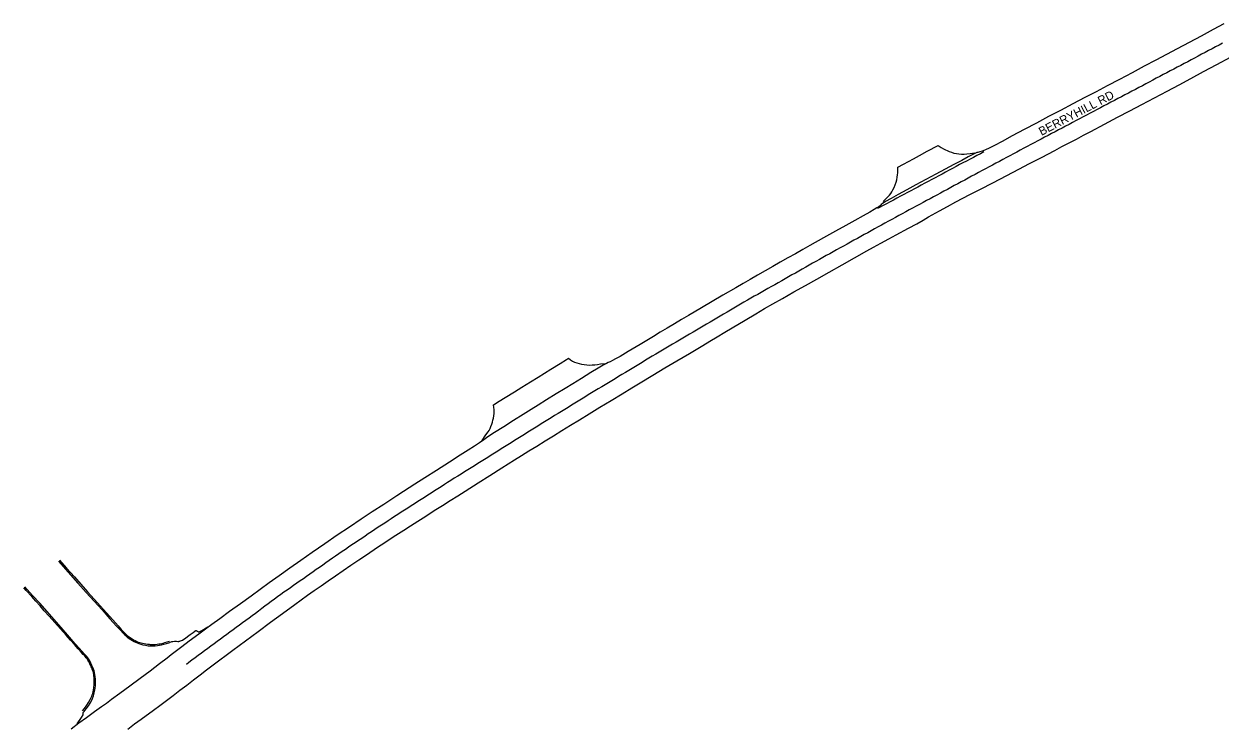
# Model space of a CAD drawing. Extents: x 1961683 to 1977751, y 798292 to 805767.
# Drawn here: x 1964029 to 1964786, y 800806 to 801250 of the extents above; entities that cross this region are included whole.
import ezdxf

# ---------------------------------------------------------------- set-up
doc = ezdxf.new("R2010")
doc.units = 0
for name, color, linetype in [('RD_EX_Road', 7, 'Continuous'), ('RD_EX_Road_Paint', 7, 'Continuous'), ('RD_TX_RoadID', 7, 'Continuous')]:
    doc.layers.add(name, color=color, linetype=linetype)

msp = doc.modelspace()

# ---------------------------------------------------------------- linework, layer by layer
at = {"layer": 'RD_EX_Road'}
for points in [[(1964788.54, 801250.42), (1964781.89, 801246.79), (1964774.38, 801242.74), (1964766.61, 801238.62), (1964759.07, 801234.65), (1964752.26, 801231.05), (1964745.53, 801227.48), (1964738.24, 801223.57), (1964730.54, 801219.46), (1964722.57, 801215.24), (1964714.81, 801211.15), (1964707.73, 801207.41), (1964700.69, 801203.7), (1964693.06, 801199.71), (1964685.24, 801195.62), (1964677.66, 801191.63), (1964670.04, 801187.61), (1964662.09, 801183.39), (1964654.57, 801179.38), (1964648.22, 801175.97), (1964643.28, 801173.36), (1964639.97, 801171.7), (1964637.64, 801170.66), (1964635.66, 801169.85), (1964634.07, 801169.3), (1964632.91, 801169.02), (1964632.3, 801168.84), (1964630.14, 801167.85), (1964626.81, 801166.08), (1964622.62, 801163.89), (1964617.66, 801161.34), (1964612.14, 801158.43), (1964606.14, 801155.19), (1964599.93, 801151.85), (1964593.63, 801148.49), (1964587.76, 801145.27), (1964582.46, 801142.26), (1964577.98, 801139.77), (1964574.44, 801137.84), (1964572.24, 801136.45), (1964571.67, 801135.95), (1964570.88, 801135.16), (1964570.05, 801134.51), (1964568.89, 801133.78), (1964567.14, 801132.73), (1964564.36, 801131.11), (1964560.13, 801128.69), (1964554.93, 801125.76), (1964549.25, 801122.63), (1964542.75, 801119.04), (1964535.08, 801114.74), (1964526.5, 801109.92), (1964521.98, 801107.38), (1964517.29, 801104.76), (1964512.51, 801102.09), (1964507.73, 801099.39), (1964502.93, 801096.67), (1964498.13, 801093.92), (1964493.36, 801091.18), (1964488.68, 801088.49), (1964484.09, 801085.84), (1964479.59, 801083.24), (1964471.4, 801078.46), (1964464.65, 801074.47), (1964457.88, 801070.46), (1964449.61, 801065.62), (1964445.12, 801062.99), (1964440.63, 801060.34), (1964436.15, 801057.68), (1964431.69, 801055), (1964427.3, 801052.36), (1964418.95, 801047.33), (1964411.42, 801042.79), (1964406.25, 801039.72), (1964403.43, 801038.11), (1964401.42, 801037.01), (1964399.93, 801036.24), (1964398.71, 801035.72), (1964397.58, 801035.29), (1964395.57, 801034.2), (1964392.45, 801032.29), (1964387.78, 801029.42), (1964381.8, 801025.74), (1964376.29, 801022.36), (1964371.35, 801019.35), (1964365.78, 801015.93), (1964359.6, 801012.14), (1964354.34, 801008.87), (1964349.95, 801006.12), (1964344.77, 801002.87), (1964338.69, 800999.04), (1964332.56, 800995.15), (1964326.74, 800991.42), (1964322.53, 800988.64), (1964319.86, 800986.79), (1964317.14, 800984.91), (1964314.02, 800982.82), (1964310.05, 800980.25), (1964305.03, 800977.06), (1964298.22, 800972.73), (1964289.92, 800967.44), (1964282.59, 800962.77), (1964276.3, 800958.74), (1964268.98, 800954), (1964264.8, 800951.27), (1964256.57, 800945.88), (1964249.29, 800941.1), (1964242.29, 800936.48), (1964234.87, 800931.56), (1964227.13, 800926.37), (1964219.14, 800920.91), (1964211.29, 800915.49), (1964203.98, 800910.41), (1964197.03, 800905.53), (1964190.29, 800900.72), (1964183.98, 800896.17), (1964178.3, 800892.03), (1964172.48, 800887.77), (1964165.72, 800882.88), (1964158.87, 800877.91), (1964152.78, 800873.45), (1964147.65, 800869.67), (1964143.69, 800866.77), (1964140.35, 800864.33), (1964137.1, 800861.91), (1964133.39, 800859.13), (1964128.65, 800855.62), (1964124.35, 800852.42), (1964121.92, 800850.56), (1964119.34, 800848.54), (1964114.55, 800844.84), (1964108.51, 800840.24), (1964102.18, 800835.5), (1964095.76, 800830.73), (1964089.43, 800826.05), (1964084.15, 800822.17), (1964080.86, 800819.8), (1964077.85, 800817.64), (1964073.39, 800814.4), (1964068.3, 800810.7), (1964063.42, 800807.16), (1964058.54, 800803.54)], [(1964094.49, 800803.53), (1964098.77, 800806.72), (1964102.88, 800809.76), (1964110.77, 800815.54), (1964114.8, 800818.53), (1964118.94, 800821.63), (1964123.18, 800824.84), (1964127.46, 800828.11), (1964131.72, 800831.36), (1964135.96, 800834.6), (1964140.18, 800837.83), (1964144.38, 800841.03), (1964148.54, 800844.19), (1964152.68, 800847.31), (1964156.78, 800850.4), (1964160.86, 800853.45), (1964164.92, 800856.48), (1964168.96, 800859.48), (1964176.97, 800865.4), (1964184.77, 800871.15), (1964192.42, 800876.76), (1964200.24, 800882.44), (1964208.32, 800888.26), (1964212.54, 800891.25), (1964216.88, 800894.31), (1964221.36, 800897.43), (1964225.97, 800900.63), (1964230.74, 800903.91), (1964235.67, 800907.28), (1964240.75, 800910.73), (1964245.52, 800913.95), (1964252.67, 800918.78), (1964257.23, 800921.81), (1964262.58, 800925.26), (1964269.37, 800929.57), (1964273.49, 800932.21), (1964278.11, 800935.19), (1964283.24, 800938.51), (1964288.54, 800941.94), (1964293.68, 800945.24), (1964298.66, 800948.4), (1964303.47, 800951.42), (1964308.07, 800954.3), (1964316.4, 800959.57), (1964323.79, 800964.29), (1964331.32, 800969.07), (1964339.31, 800974.06), (1964343.72, 800976.81), (1964348.45, 800979.75), (1964353.51, 800982.88), (1964358.75, 800986.13), (1964364.05, 800989.4), (1964369.41, 800992.72), (1964374.83, 800996.06), (1964380.52, 800999.57), (1964386.72, 801003.36), (1964393.41, 801007.43), (1964400.6, 801011.8), (1964407.59, 801016.03), (1964413.68, 801019.72), (1964418.88, 801022.87), (1964427, 801027.8), (1964434.58, 801032.36), (1964442.13, 801036.85), (1964450.12, 801041.61), (1964458.66, 801046.69), (1964463.15, 801049.38), (1964467.81, 801052.15), (1964472.63, 801055.03), (1964477.32, 801057.83), (1964485.49, 801062.69), (1964492.13, 801066.62), (1964497.8, 801069.95), (1964502.88, 801072.91), (1964509.01, 801076.42), (1964516.28, 801080.55), (1964523.59, 801084.67), (1964530.85, 801088.74), (1964538.61, 801093.11), (1964546.84, 801097.77), (1964554.78, 801102.22), (1964562.51, 801106.5), (1964566.78, 801108.86), (1964571.4, 801111.39), (1964576.36, 801114.1), (1964581.18, 801116.73), (1964588.89, 801120.92), (1964594.2, 801123.81), (1964598.14, 801126.08), (1964601.58, 801128.16), (1964608.56, 801132.04), (1964613.63, 801134.78), (1964618.94, 801137.61), (1964627.74, 801142.2), (1964634.61, 801145.64), (1964642.37, 801149.63), (1964651.14, 801154.26), (1964658.9, 801158.34), (1964665.6, 801161.85), (1964673.09, 801165.79), (1964681.59, 801170.27), (1964686.04, 801172.62), (1964690.58, 801175.02), (1964695.22, 801177.47), (1964699.86, 801179.92), (1964704.39, 801182.32), (1964713.12, 801186.93), (1964721.35, 801191.29), (1964729.03, 801195.33), (1964736.66, 801199.35), (1964744.71, 801203.59), (1964752.73, 801207.83), (1964760.26, 801211.84), (1964767.79, 801215.87), (1964775.78, 801220.18), (1964784.19, 801224.71), (1964792.92, 801229.36)], [(1964572.94, 801137.8), (1964575.36, 801140.33), (1964576.79, 801141.93), (1964577.65, 801143.03), (1964578.34, 801144.09), (1964578.99, 801145.29), (1964579.73, 801146.82), (1964580.44, 801148.48), (1964581, 801150.11), (1964581.44, 801151.68), (1964581.81, 801153.19), (1964582.05, 801154.66), (1964582.15, 801156.09), (1964582.17, 801157.67), (1964582.19, 801159.6), (1964585.84, 801161.54), (1964588.93, 801163.25), (1964592.06, 801165), (1964595.81, 801167.06), (1964600.81, 801169.73), (1964607.68, 801173.3), (1964609.59, 801172.16), (1964611.05, 801171.31), (1964612.25, 801170.66), (1964613.39, 801170.11), (1964614.63, 801169.59), (1964616.11, 801169.06), (1964617.7, 801168.58), (1964619.24, 801168.25), (1964620.81, 801168.03), (1964622.5, 801167.9), (1964624.22, 801167.89), (1964625.88, 801167.99), (1964627.95, 801168.25), (1964630.89, 801168.74)], [(1964318.91, 800986.48), (1964320.79, 800989.45), (1964321.84, 800990.73), (1964322.63, 800991.79), (1964323.27, 800992.78), (1964323.85, 800993.89), (1964324.43, 800995.27), (1964324.95, 800996.71), (1964325.35, 800998), (1964325.67, 800999.26), (1964325.96, 801000.63), (1964326.21, 801002.05), (1964326.38, 801003.49), (1964326.45, 801004.85), (1964326.4, 801006.06), (1964326.27, 801007.38), (1964326.11, 801009.08), (1964329.69, 801011.28), (1964333.46, 801013.6), (1964339.4, 801017.31), (1964343.92, 801020.14), (1964349.49, 801023.63), (1964354.37, 801026.6), (1964362.42, 801031.52), (1964368.27, 801035.12), (1964372.27, 801037.64), (1964373.6, 801038.51), (1964374.84, 801037.58), (1964376.13, 801036.74), (1964377.45, 801036.04), (1964378.82, 801035.54), (1964380.26, 801035.17), (1964381.8, 801034.84), (1964383.43, 801034.56), (1964385.17, 801034.34), (1964386.93, 801034.22), (1964388.65, 801034.25), (1964390.3, 801034.38), (1964391.89, 801034.58), (1964393.74, 801034.93), (1964396.9, 801035.23)], [(1964050.52, 800909.9), (1964056.68, 800902.99), (1964062.83, 800896.07), (1964068.15, 800890.09), (1964073.19, 800884.47), (1964078.12, 800878.98), (1964083.15, 800873.42), (1964087.34, 800868.79), (1964089.78, 800866.1), (1964091.25, 800864.52), (1964092.55, 800863.23), (1964093.54, 800862.31), (1964094.06, 800861.84), (1964094.52, 800861.49), (1964095.34, 800860.91), (1964096.34, 800860.25), (1964097.35, 800859.62), (1964098.37, 800859.04), (1964099.39, 800858.51), (1964100.42, 800858.05), (1964101.47, 800857.65), (1964102.63, 800857.28), (1964104.01, 800856.94), (1964105.56, 800856.63), (1964107.26, 800856.35), (1964108.93, 800856.18), (1964110.39, 800856.15), (1964111.77, 800856.25), (1964113.19, 800856.43), (1964114.57, 800856.65), (1964115.81, 800856.88), (1964117.16, 800857.21), (1964118.87, 800857.71), (1964120.33, 800858.17), (1964120.95, 800858.35), (1964121.31, 800858.48), (1964121.95, 800858.77), (1964122.38, 800858.93), (1964122.87, 800859.04), (1964124.04, 800859.15), (1964125.19, 800859.14), (1964126.06, 800859.1), (1964126.69, 800859.08), (1964126.95, 800859.11), (1964127.37, 800859.22), (1964127.86, 800859.36), (1964128.45, 800859.54), (1964129.15, 800859.87), (1964129.98, 800860.38), (1964131.01, 800861.12), (1964132.29, 800862.1), (1964133.91, 800863.35), (1964135.74, 800864.75), (1964136.81, 800865.57), (1964137.08, 800865.77), (1964137.17, 800865.81), (1964137.26, 800865.85), (1964137.47, 800865.91), (1964137.57, 800865.93), (1964137.67, 800865.93), (1964137.76, 800865.93), (1964137.85, 800865.92), (1964137.94, 800865.89), (1964138.03, 800865.85), (1964138.21, 800865.73), (1964138.46, 800865.54), (1964138.77, 800865.29), (1964138.91, 800865.2), (1964139.03, 800865.14), (1964139.13, 800865.11), (1964139.23, 800865.1), (1964139.36, 800865.11), (1964139.7, 800865.19), (1964141.24, 800866.04), (1964145.08, 800868.39)], [(1964051.21, 800910.52), (1964055.68, 800905.53), (1964060.61, 800899.99), (1964064.77, 800895.3), (1964069, 800890.54), (1964073.16, 800885.88), (1964077.11, 800881.48), (1964081, 800877.14), (1964085, 800872.66), (1964088.35, 800868.9), (1964090.32, 800866.69), (1964091.53, 800865.36), (1964092.6, 800864.25), (1964093.46, 800863.41), (1964094.06, 800862.86), (1964094.62, 800862.41), (1964095.37, 800861.86), (1964096.23, 800861.27), (1964097.16, 800860.67), (1964098.14, 800860.09), (1964099.16, 800859.55), (1964100.16, 800859.07), (1964101.1, 800858.68), (1964102.01, 800858.36), (1964102.91, 800858.11), (1964103.84, 800857.9), (1964104.81, 800857.72), (1964105.83, 800857.55), (1964106.9, 800857.38), (1964107.89, 800857.25), (1964108.68, 800857.17), (1964109.5, 800857.13), (1964110.61, 800857.12), (1964111.82, 800857.16), (1964112.95, 800857.28), (1964114.01, 800857.45), (1964115, 800857.61), (1964115.92, 800857.8), (1964116.75, 800858.01), (1964117.92, 800858.36), (1964120.88, 800859.26)], [(1964065.67, 800815.04), (1964066.94, 800816.64), (1964068.42, 800818.61), (1964069.54, 800820.32), (1964070.61, 800822.23), (1964071.25, 800823.42), (1964071.64, 800824.26), (1964071.95, 800825.15), (1964072.22, 800826.08), (1964072.47, 800827.06), (1964072.7, 800828.26), (1964072.95, 800829.84), (1964073.13, 800831.5), (1964073.19, 800832.94), (1964073.17, 800834.18), (1964073.13, 800835.24), (1964073.07, 800836.21), (1964072.97, 800837.2), (1964072.82, 800838.17), (1964072.63, 800839.08), (1964072.4, 800839.93), (1964072.17, 800840.73), (1964071.92, 800841.49), (1964071.63, 800842.21), (1964071.29, 800842.98), (1964070.9, 800843.85), (1964070.46, 800844.78), (1964069.99, 800845.71), (1964069.54, 800846.54), (1964069.17, 800847.18), (1964068.83, 800847.71), (1964068.49, 800848.21), (1964068.12, 800848.69), (1964067.71, 800849.18), (1964067.12, 800849.82), (1964066.23, 800850.8), (1964064.9, 800852.28), (1964062.99, 800854.42), (1964060.69, 800857), (1964058.21, 800859.79), (1964055.32, 800863.02), (1964051.81, 800866.96), (1964048.12, 800871.12), (1964044.68, 800874.99), (1964041.56, 800878.51), (1964038.83, 800881.59), (1964036.24, 800884.51), (1964033.56, 800887.53), (1964030.1, 800891.4), (1964028.63, 800893.02)], [(1964062.32, 800806.88), (1964065.05, 800810.85), (1964066.08, 800812.53), (1964066.21, 800812.99), (1964066.23, 800813.16), (1964066.22, 800813.29), (1964066.19, 800813.5), (1964066.15, 800813.69), (1964066.14, 800813.78), (1964066.15, 800813.86), (1964066.18, 800813.94), (1964066.23, 800814.02), (1964066.73, 800814.65), (1964068.01, 800816.25), (1964069.49, 800818.22), (1964070.61, 800819.93), (1964071.45, 800821.47), (1964072.08, 800822.95), (1964072.61, 800824.53), (1964073.12, 800826.41), (1964073.55, 800828.24), (1964073.81, 800829.71), (1964073.94, 800830.96), (1964073.99, 800832.13), (1964074, 800833.2), (1964073.97, 800834.18), (1964073.91, 800835.27), (1964073.8, 800836.67), (1964073.64, 800838.12), (1964073.4, 800839.36), (1964073.11, 800840.43), (1964072.79, 800841.39), (1964072.36, 800842.46), (1964071.74, 800843.87), (1964071.03, 800845.35), (1964070.34, 800846.66), (1964069.51, 800847.96), (1964068.38, 800849.4), (1964067.02, 800850.99), (1964065.5, 800852.72), (1964063.62, 800854.85), (1964061.18, 800857.62), (1964056.31, 800863.21), (1964052.26, 800867.9), (1964047.87, 800872.86), (1964043.26, 800878.01), (1964038.62, 800883.2), (1964034.15, 800888.21), (1964030.76, 800892.01), (1964029.31, 800893.63)]]:
    msp.add_lwpolyline(points, dxfattribs=at)
at = {"layer": 'RD_EX_Road_Paint'}
for points in [[(1964787.8, 801238.23), (1964785.59, 801237.05), (1964783.39, 801235.87), (1964781.19, 801234.69), (1964778.98, 801233.51), (1964776.78, 801232.33), (1964774.57, 801231.15), (1964772.37, 801229.97), (1964770.16, 801228.8), (1964767.95, 801227.63), (1964765.75, 801226.46), (1964763.54, 801225.29), (1964761.33, 801224.12), (1964759.12, 801222.95), (1964756.91, 801221.78), (1964754.7, 801220.61), (1964752.5, 801219.44), (1964750.29, 801218.27), (1964748.08, 801217.1), (1964745.87, 801215.93), (1964743.66, 801214.76), (1964741.45, 801213.59), (1964739.25, 801212.42), (1964737.04, 801211.25), (1964734.83, 801210.09), (1964732.62, 801208.92), (1964730.41, 801207.75), (1964728.2, 801206.59), (1964725.99, 801205.42), (1964723.78, 801204.25), (1964721.57, 801203.09), (1964719.36, 801201.92), (1964717.15, 801200.75), (1964714.94, 801199.59), (1964712.73, 801198.42), (1964710.52, 801197.25), (1964708.31, 801196.09), (1964706.1, 801194.92), (1964703.89, 801193.76), (1964701.68, 801192.59), (1964699.47, 801191.43), (1964697.26, 801190.26), (1964695.05, 801189.1), (1964692.84, 801187.93), (1964690.63, 801186.77), (1964688.42, 801185.6), (1964686.21, 801184.44), (1964684, 801183.27), (1964681.79, 801182.11), (1964679.58, 801180.94), (1964677.37, 801179.78), (1964675.16, 801178.61), (1964672.95, 801177.45), (1964670.74, 801176.28), (1964668.53, 801175.11), (1964666.33, 801173.93), (1964664.13, 801172.75), (1964661.93, 801171.57), (1964659.72, 801170.39), (1964657.52, 801169.21), (1964655.32, 801168.03), (1964653.12, 801166.85), (1964650.92, 801165.67), (1964648.72, 801164.49), (1964646.51, 801163.31), (1964644.31, 801162.13), (1964642.11, 801160.95), (1964639.91, 801159.77), (1964637.71, 801158.59), (1964635.5, 801157.41), (1964633.3, 801156.23), (1964631.11, 801155.04), (1964628.91, 801153.86), (1964626.71, 801152.67), (1964624.52, 801151.48), (1964622.32, 801150.29), (1964620.13, 801149.1), (1964617.93, 801147.91), (1964615.73, 801146.72), (1964613.54, 801145.53), (1964611.34, 801144.34), (1964609.15, 801143.15), (1964606.95, 801141.96), (1964604.75, 801140.78), (1964602.55, 801139.59), (1964600.35, 801138.41), (1964598.15, 801137.23), (1964595.95, 801136.05), (1964593.75, 801134.86), (1964591.55, 801133.68), (1964589.35, 801132.5), (1964587.15, 801131.32), (1964584.96, 801130.12), (1964582.77, 801128.92), (1964580.58, 801127.72), (1964578.39, 801126.52), (1964576.2, 801125.32), (1964574.02, 801124.11), (1964571.83, 801122.91), (1964569.64, 801121.71), (1964567.45, 801120.51), (1964565.26, 801119.31), (1964563.08, 801118.1), (1964560.89, 801116.89), (1964558.71, 801115.68), (1964556.52, 801114.47), (1964554.34, 801113.26), (1964552.15, 801112.05), (1964549.97, 801110.84), (1964547.78, 801109.63), (1964545.6, 801108.42), (1964543.41, 801107.21), (1964541.23, 801106), (1964539.05, 801104.79), (1964536.86, 801103.59), (1964534.68, 801102.38), (1964532.5, 801101.16), (1964530.32, 801099.92), (1964528.15, 801098.69), (1964525.98, 801097.46), (1964523.81, 801096.23), (1964521.64, 801095), (1964519.46, 801093.76), (1964517.29, 801092.53), (1964515.12, 801091.3), (1964512.95, 801090.07), (1964510.78, 801088.84), (1964508.6, 801087.6), (1964506.43, 801086.37), (1964504.26, 801085.14), (1964502.09, 801083.91), (1964499.92, 801082.68), (1964497.74, 801081.44), (1964495.57, 801080.22), (1964493.39, 801078.99), (1964491.22, 801077.76), (1964489.05, 801076.53), (1964486.87, 801075.3), (1964484.7, 801074.07), (1964482.54, 801072.82), (1964480.4, 801071.54), (1964478.25, 801070.26), (1964476.11, 801068.97), (1964473.97, 801067.69), (1964471.81, 801066.43), (1964469.66, 801065.17), (1964467.5, 801063.91), (1964465.35, 801062.65), (1964463.19, 801061.39), (1964461.03, 801060.13), (1964458.88, 801058.86), (1964456.73, 801057.6), (1964454.57, 801056.34), (1964452.42, 801055.08), (1964450.26, 801053.81), (1964448.11, 801052.55), (1964445.96, 801051.29), (1964443.81, 801050.01), (1964441.66, 801048.74), (1964439.51, 801047.47), (1964437.37, 801046.19), (1964435.22, 801044.92), (1964433.07, 801043.64), (1964430.92, 801042.37), (1964428.78, 801041.1), (1964426.63, 801039.82), (1964424.5, 801038.52), (1964422.37, 801037.22), (1964420.23, 801035.92), (1964418.1, 801034.63), (1964415.97, 801033.33), (1964413.83, 801032.03), (1964411.7, 801030.73), (1964409.57, 801029.43), (1964407.43, 801028.14), (1964405.3, 801026.85), (1964403.15, 801025.56), (1964401.01, 801024.28), (1964398.87, 801022.99), (1964396.73, 801021.7), (1964394.59, 801020.42), (1964392.45, 801019.13), (1964390.31, 801017.85), (1964388.18, 801016.55), (1964386.05, 801015.24), (1964383.92, 801013.94), (1964381.8, 801012.63), (1964379.67, 801011.32), (1964377.54, 801010.02), (1964375.41, 801008.71), (1964373.28, 801007.4), (1964371.16, 801006.09), (1964369.04, 801004.77), (1964366.92, 801003.45), (1964364.8, 801002.14), (1964362.68, 801000.82), (1964360.55, 800999.51), (1964358.43, 800998.19), (1964356.31, 800996.88), (1964354.19, 800995.56), (1964352.07, 800994.24), (1964349.95, 800992.92), (1964347.83, 800991.6), (1964345.71, 800990.28), (1964343.59, 800988.96), (1964341.47, 800987.64), (1964339.35, 800986.32), (1964337.23, 800985), (1964335.11, 800983.68), (1964332.99, 800982.35), (1964330.88, 800981.02), (1964328.77, 800979.69), (1964326.65, 800978.36), (1964324.54, 800977.03), (1964322.43, 800975.7), (1964320.31, 800974.37), (1964318.2, 800973.04), (1964316.08, 800971.72), (1964313.96, 800970.4), (1964311.84, 800969.08), (1964309.73, 800967.75), (1964307.61, 800966.43), (1964305.49, 800965.11), (1964303.37, 800963.79), (1964301.25, 800962.46), (1964299.13, 800961.14), (1964297.02, 800959.81), (1964294.92, 800958.46), (1964292.82, 800957.1), (1964290.72, 800955.75), (1964288.62, 800954.4), (1964286.52, 800953.05), (1964284.42, 800951.69), (1964282.32, 800950.34), (1964280.22, 800948.99), (1964278.12, 800947.64), (1964276.02, 800946.28), (1964273.93, 800944.93), (1964271.83, 800943.57), (1964269.73, 800942.22), (1964267.63, 800940.87), (1964265.53, 800939.51), (1964263.43, 800938.16), (1964261.33, 800936.8), (1964259.24, 800935.45), (1964257.14, 800934.09), (1964255.04, 800932.74), (1964252.96, 800931.36), (1964250.89, 800929.96), (1964248.81, 800928.57), (1964246.74, 800927.17), (1964244.67, 800925.78), (1964242.6, 800924.38), (1964240.52, 800922.99), (1964238.45, 800921.59), (1964236.38, 800920.2), (1964234.31, 800918.8), (1964232.23, 800917.41), (1964230.16, 800916.01), (1964228.09, 800914.62), (1964226.05, 800913.18), (1964224, 800911.74), (1964221.96, 800910.3), (1964219.92, 800908.87), (1964217.87, 800907.43), (1964215.83, 800905.99), (1964213.79, 800904.55), (1964211.74, 800903.11), (1964209.7, 800901.68), (1964207.66, 800900.24), (1964205.61, 800898.8), (1964203.57, 800897.36), (1964201.52, 800895.93), (1964199.48, 800894.49), (1964197.44, 800893.05), (1964195.39, 800891.61), (1964193.35, 800890.17), (1964191.33, 800888.71), (1964189.31, 800887.23), (1964187.3, 800885.75), (1964185.29, 800884.26), (1964183.28, 800882.78), (1964181.26, 800881.3), (1964179.25, 800879.82), (1964177.24, 800878.33), (1964175.23, 800876.85), (1964173.22, 800875.37), (1964171.2, 800873.89), (1964169.19, 800872.4), (1964167.18, 800870.92), (1964165.17, 800869.44), (1964163.16, 800867.96), (1964161.14, 800866.47), (1964159.14, 800864.98), (1964157.13, 800863.49), (1964155.13, 800862), (1964153.12, 800860.51), (1964151.11, 800859.02), (1964149.11, 800857.53), (1964147.1, 800856.04), (1964145.09, 800854.55), (1964143.09, 800853.06), (1964141.08, 800851.57), (1964139.07, 800850.08), (1964137.07, 800848.59), (1964135.06, 800847.1), (1964133.06, 800845.6), (1964131.54, 800844.48)], [(1964636.73, 801169.29), (1964634.51, 801168.13), (1964632.3, 801166.98), (1964630.08, 801165.83), (1964627.87, 801164.67), (1964625.65, 801163.52), (1964623.43, 801162.37), (1964621.22, 801161.21), (1964619.02, 801160.02), (1964616.82, 801158.84), (1964614.63, 801157.65), (1964612.43, 801156.47), (1964610.23, 801155.29), (1964608.03, 801154.11), (1964605.83, 801152.93), (1964603.63, 801151.75), (1964601.42, 801150.57), (1964599.22, 801149.39), (1964597.02, 801148.22), (1964594.82, 801147.04), (1964592.61, 801145.87), (1964590.41, 801144.7), (1964588.21, 801143.52), (1964586.01, 801142.33), (1964583.81, 801141.14), (1964581.62, 801139.96), (1964579.42, 801138.77), (1964577.22, 801137.59), (1964575.02, 801136.42), (1964572.81, 801135.24), (1964570.61, 801134.06), (1964569.37, 801133.4)]]:
    msp.add_lwpolyline(points, dxfattribs=at)

# ---------------------------------------------------------------- texts
at = {"layer": 'RD_TX_RoadID'}
msp.add_text('BERRYHILL RD', height=5.4, rotation=27.49506, dxfattribs=at).set_placement((1964673.13, 801179.42))

doc.saveas('drawing.dxf')
